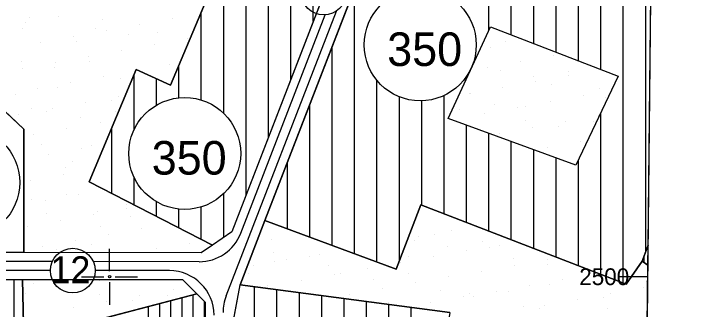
# Model space of a CAD drawing. Extents: x 419109 to 421295, y 4452223 to 4457798.
# Drawn here: x 420957.3 to 421266.4, y 4452485.5 to 4452617.5 of the extents above; entities that cross this region are included whole.
import ezdxf

# ---------------------------------------------------------------- set-up
doc = ezdxf.new("R2010")
doc.units = 0
for name, color, linetype in [('ADA', 7, 'Continuous'), ('ADAKENARI', 7, 'Continuous'), ('Default', 7, 'Continuous'), ('KALDIRIM', 7, 'Continuous'), ('KD_DAIRE', 7, 'Continuous'), ('KD_YGEN', 7, 'Continuous'), ('PAFTALAMA', 7, 'Continuous'), ('PL_AYA_PARK_DINLENME', 7, 'Continuous'), ('PL_KON_MEV_350', 7, 'Continuous'), ('PL_KON_MEV_450', 7, 'Continuous'), ('SM_DAIRE', 7, 'Continuous'), ('SM_TAKS', 7, 'Continuous'), ('TR_ORTAYOGUNKONUT', 7, 'Continuous'), ('TR_PARKALANI', 7, 'Continuous'), ('TR_YUKSEKYOGUNKONUT', 7, 'Continuous')]:
    doc.layers.add(name, color=color, linetype=linetype)

# ---------------------------------------------------------------- blocks, each defined once
blk = doc.blocks.new('POINT_DISPLAY')
at = {"layer": 'Default'}
blk.add_line((0, 0), (0, 0), dxfattribs=at)

msp = doc.modelspace()

# ---------------------------------------------------------------- linework, layer by layer
at = {"layer": 'ADA'}
for p, q in [((421027.16, 4452585.56), (421111.62, 4452786.24)), ((420907.13, 4452617.31), (420961.75, 4452565.87)), ((421151.16, 4452570.72), (421170.06, 4452611.68)), ((421170.06, 4452611.68), (421227.17, 4452589.62)), ((420990.96, 4452542.37), (421011.92, 4452592.54)), ((421011.92, 4452592.54), (421027.16, 4452585.56)), ((421227.17, 4452589.62), (421208.27, 4452549.84)), ((421208.27, 4452549.84), (421151.16, 4452570.72)), ((420961.75, 4452565.87), (420961.75, 4452510.75)), ((421045.97, 4452514.14), (420990.96, 4452542.37)), ((421127.92, 4452503.37), (421138.95, 4452532.12)), ((421138.95, 4452532.12), (421230.72, 4452496.67)), ((421069.4, 4452525.16), (421127.92, 4452503.37)), ((421237.81, 4452506.91), (421240.5, 4452514.11)), ((421230.72, 4452496.67), (421237.81, 4452506.91)), ((421237.81, 4452506.91), (421240.41, 4452505.19)), ((420961.13, 4452498.75), (420961.65, 4452472.06)), ((421151.95, 4452484.07), (421058.29, 4452496.43)), ((420961.65, 4452472.06), (421038.96, 4452492.38))]:
    msp.add_line(p, q, dxfattribs=at)
at = {"layer": 'ADAKENARI'}
for p, q in [((421113.68, 4452672.92), (421054.54, 4452520.01)), ((421069.4, 4452525.16), (421125.97, 4452671.42)), ((421058.29, 4452496.43), (421069.4, 4452525.16)), ((421054.54, 4452520.01), (421045.97, 4452514.14)), ((421045.97, 4452514.14), (421040.93, 4452510.69)), ((420961.75, 4452510.75), (420907.18, 4452510.79)), ((421040.93, 4452510.69), (420961.75, 4452510.75)), ((420915.8, 4452498.79), (420961.13, 4452498.75)), ((420961.13, 4452498.75), (421032.6, 4452498.7)), ((421032.6, 4452498.7), (421038.96, 4452492.38)), ((421054.75, 4452477.11), (421058.29, 4452496.43)), ((421038.96, 4452492.38), (421042.67, 4452488.69)), ((421042.67, 4452488.69), (421043.46, 4452373.99))]:
    msp.add_line(p, q, dxfattribs=at)
at = {"layer": 'KALDIRIM'}
for p, q in [((421052.05, 4452491.39), (421101.28, 4452618.69)), ((421058.62, 4452519.48), (421096.33, 4452616.98)), ((420974.4, 4452506.74), (420878.15, 4452506.82)), ((421039.95, 4452506.69), (420992.72, 4452506.73)), ((420973.56, 4452502.74), (420878.31, 4452502.82)), ((421026.72, 4452502.7), (420993.56, 4452502.73))]:
    msp.add_line(p, q, dxfattribs=at)
for centre, start, end in [((421039.97, 4452526.69), 269.9569, 338.8546), ((421026.71, 4452482.7), 0.3974, 89.9569), ((421070.7, 4452484.17), 158.8546, 180.3974)]:
    msp.add_arc(centre, 20, start, end, dxfattribs=at)
at = {"layer": 'KD_DAIRE'}
for centre in [(421095.66, 4452626.96), (420983.56, 4452502.72)]:
    msp.add_circle(centre, 10, dxfattribs=at)
at = {"layer": 'PAFTALAMA'}
for p, q in [((421000, 4452502.5), (421000, 4452512.5)), ((420987.5, 4452500), (420997.5, 4452500)), ((421002.5, 4452500), (421012.5, 4452500)), ((421240.35, 4452500), (421227.85, 4452500)), ((421240.35, 4452500), (421240.35, 4452500)), ((421000, 4452497.5), (421000, 4452487.5))]:
    msp.add_line(p, q, dxfattribs=at)
msp.add_lwpolyline([(419138.44, 4455021.89), (419108.72, 4452245.78), (421237.47, 4452223.29), (421266.41, 4454999.4)], dxfattribs=at)
msp.add_circle((421000, 4452500), 0.5, dxfattribs=at)
at = {"layer": 'PL_AYA_PARK_DINLENME'}
msp.add_line((421239.55, 4452422.72), (421240.41, 4452505.19), dxfattribs=at)
for points in [[(421111.62, 4452786.24), (421027.16, 4452585.56), (421011.92, 4452592.54), (420990.96, 4452542.37), (421045.97, 4452514.14), (421040.93, 4452510.69), (420961.75, 4452510.75), (420961.75, 4452565.87), (420907.13, 4452617.31), (420862.44, 4452616.65), (420862.05, 4452637.03)], [(421240.41, 4452505.19), (421237.81, 4452506.91), (421230.72, 4452496.67), (421138.95, 4452532.12), (421127.92, 4452503.37), (421069.4, 4452525.16), (421058.29, 4452496.43), (421151.95, 4452484.07), (421150.76, 4452476.19), (421221.66, 4452469.5), (421219.69, 4452425.78), (421239.55, 4452422.72)]]:
    msp.add_lwpolyline(points, dxfattribs=at)
for points in [[(421208.27, 4452549.84), (421151.16, 4452570.72), (421170.06, 4452611.68), (421227.17, 4452589.62)], [(421038.96, 4452492.38), (420961.65, 4452472.06), (420961.13, 4452498.75), (421032.6, 4452498.7)]]:
    msp.add_lwpolyline(points, close=True, dxfattribs=at)
at = {"layer": 'PL_KON_MEV_350'}
for points in [[(421168.9, 4452817.73), (421120.85, 4452691.59), (421113.68, 4452672.92), (421054.54, 4452520.01), (421045.97, 4452514.14), (420990.96, 4452542.37), (421011.92, 4452592.54), (421027.16, 4452585.56), (421111.62, 4452786.24), (421094.47, 4452793.22), (421114.79, 4452841.49)], [(420961.75, 4452510.75), (420907.18, 4452510.79), (420907.13, 4452617.31), (420961.75, 4452565.87)], [(421221.66, 4452469.5), (421219.69, 4452425.78), (421204.43, 4452417.65), (421149.96, 4452423.83), (421144.17, 4452390.8), (421167.72, 4452387.62), (421148.77, 4452268.26), (421066.1, 4452275.66), (421056.07, 4452286.55), (421054.75, 4452477.11), (421058.29, 4452496.43), (421151.95, 4452484.07), (421150.76, 4452476.19)]]:
    msp.add_lwpolyline(points, close=True, dxfattribs=at)
for points in [[(421241.81, 4452639.69), (421138.97, 4452677.31), (421125.97, 4452671.42), (421069.4, 4452525.16), (421127.92, 4452503.37), (421138.95, 4452532.12), (421230.72, 4452496.67), (421237.81, 4452506.91), (421240.5, 4452514.11)], [(421240.5, 4452514.11), (421241.25, 4452585.52), (421241.81, 4452639.69)], [(421208.27, 4452549.84), (421151.16, 4452570.72), (421170.06, 4452611.68), (421227.17, 4452589.62), (421208.27, 4452549.84)]]:
    msp.add_lwpolyline(points, dxfattribs=at)
at = {"layer": 'PL_KON_MEV_450'}
msp.add_line((421240.41, 4452505.19), (421240.5, 4452514.11), dxfattribs=at)
msp.add_lwpolyline([(421240.5, 4452514.11), (421237.81, 4452506.91), (421240.41, 4452505.19)], dxfattribs=at)
msp.add_lwpolyline([(420943.96, 4452333.26), (420890.44, 4452339.16), (420894.07, 4452409.01), (420955.76, 4452406.29), (420930.36, 4452451.2), (420906.49, 4452429.99), (420877.39, 4452460.37), (420915.8, 4452498.79), (420961.13, 4452498.75), (420961.65, 4452472.06), (421038.96, 4452492.38), (421042.67, 4452488.69), (421043.46, 4452373.99), (421023.35, 4452363.2), (421036.05, 4452320.56), (420975.68, 4452283.75), (420939.98, 4452286.94)], close=True, dxfattribs=at)
at = {"layer": 'SM_DAIRE'}
for centre in [(421138.72, 4452603.61), (421033.56, 4452555.08), (420934.87, 4452542.14)]:
    msp.add_circle(centre, 25, dxfattribs=at)
at = {"layer": 'TR_ORTAYOGUNKONUT'}
for p, q in [((421090.96, 4452614.17), (421090.96, 4452737.15)), ((421080.96, 4452588.32), (421080.96, 4452713.39)), ((421070.96, 4452562.46), (421070.96, 4452689.63)), ((421060.96, 4452536.61), (421060.96, 4452665.87)), ((421169.4, 4452610.24), (421169.4, 4452666.18)), ((421179.4, 4452608.07), (421179.4, 4452662.52)), ((421189.4, 4452604.21), (421189.4, 4452658.86)), ((421199.4, 4452600.35), (421199.4, 4452655.21)), ((421209.4, 4452596.49), (421209.4, 4452651.55)), ((421219.4, 4452592.63), (421219.4, 4452647.89)), ((421229.4, 4452497.18), (421229.4, 4452644.23)), ((421050.96, 4452573.03), (421050.96, 4452642.11)), ((421239.4, 4452511.16), (421239.4, 4452640.57)), ((421109.4, 4452510.27), (421109.4, 4452628.58)), ((421040.96, 4452578.96), (421040.96, 4452618.35)), ((421099.4, 4452513.99), (421099.4, 4452602.73)), ((421030.96, 4452579.94), (421030.96, 4452594.59)), ((421010.96, 4452565.77), (421010.96, 4452590.25)), ((421020.96, 4452576.67), (421020.96, 4452588.4)), ((421159.4, 4452588.57), (421159.4, 4452589.57)), ((421119.4, 4452506.54), (421119.4, 4452587.75)), ((421129.4, 4452507.22), (421129.4, 4452580.42)), ((421149.4, 4452528.08), (421149.4, 4452581.01)), ((421089.4, 4452517.71), (421089.4, 4452576.87)), ((421139.4, 4452531.95), (421139.4, 4452578.62)), ((421219.4, 4452501.04), (421219.4, 4452573.26)), ((421159.4, 4452524.22), (421159.4, 4452567.71)), ((421000.96, 4452537.24), (421000.96, 4452566.31)), ((421169.4, 4452520.36), (421169.4, 4452564.05)), ((421179.4, 4452516.5), (421179.4, 4452560.4)), ((421189.4, 4452512.63), (421189.4, 4452556.74)), ((421079.4, 4452521.44), (421079.4, 4452551.02)), ((421199.4, 4452508.77), (421199.4, 4452553.09)), ((421209.4, 4452504.91), (421209.4, 4452552.22)), ((421010.96, 4452532.11), (421010.96, 4452544.39)), ((421050.96, 4452517.56), (421050.96, 4452537.13)), ((421020.96, 4452526.98), (421020.96, 4452533.48)), ((421030.96, 4452521.85), (421030.96, 4452530.21)), ((421040.96, 4452516.72), (421040.96, 4452531.2)), ((421064.75, 4452277.13), (421064.75, 4452495.58)), ((421074.75, 4452406.61), (421074.75, 4452494.26)), ((421084.75, 4452419.17), (421084.75, 4452492.94)), ((421094.75, 4452422.9), (421094.75, 4452491.62)), ((421104.75, 4452422.29), (421104.75, 4452490.3)), ((421114.75, 4452416.95), (421114.75, 4452488.98)), ((421124.75, 4452270.41), (421124.75, 4452487.66)), ((421134.75, 4452269.52), (421134.75, 4452486.34))]:
    msp.add_line(p, q, dxfattribs=at)
at = {"layer": 'TR_YUKSEKYOGUNKONUT'}
for p, q in [((421238.77, 4452506.27), (421238.77, 4452509.48)), ((420957.39, 4452285.38), (420957.39, 4452498.76)), ((421027.39, 4452365.37), (421027.39, 4452489.34)), ((421032.39, 4452368.05), (421032.39, 4452490.65)), ((421037.39, 4452370.73), (421037.39, 4452491.97)), ((421017.39, 4452309.18), (421017.39, 4452486.71)), ((421022.39, 4452312.23), (421022.39, 4452488.03)), ((421042.39, 4452373.41), (421042.39, 4452488.97))]:
    msp.add_line(p, q, dxfattribs=at)

# ---------------------------------------------------------------- block references
at = {"layer": 'TR_PARKALANI', "xscale": 0.1, "yscale": 0.10000000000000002}
for p in [(420964.23, 4452615.94), (420977.21, 4452616.39), (420962.44, 4452613.79), (420996.93, 4452614.77), (421028.19, 4452615.23), (420961.1, 4452610.81), (420993.77, 4452610.73), (420998.64, 4452610.02), (421013.41, 4452612.62), (420983.87, 4452607.41), (421008.54, 4452608.13), (421021.28, 4452609.09), (420969.1, 4452604.81), (420985.44, 4452605.13), (421020.07, 4452603.64), (421034.85, 4452606.25), (421176.94, 4452605.16), (421005.3, 4452601.04), (421170.25, 4452602.23), (420990.53, 4452598.43), (421198.38, 4452598.79), (420960.75, 4452596.24), (420975.76, 4452595.83), (420991.17, 4452595.96), (421026.74, 4452594.66), (421183.6, 4452596.18), (420960.99, 4452593.22), (420975.52, 4452593.64), (421168.83, 4452593.58), (421174.4, 4452591.93), (421204.82, 4452591.65), (421219.81, 4452592.41), (420997.19, 4452589.45), (421005.07, 4452588.43), (421189.18, 4452589.33), (421205.04, 4452589.81), (420982.42, 4452586.85), (421190.26, 4452587.2), (421197.2, 4452585.68), (420967.65, 4452584.24), (420976.55, 4452584.61), (421160.72, 4452581.99), (421175.49, 4452584.6), (421218.72, 4452584.12), (420958.15, 4452581.47), (421000.9, 4452578.93), (421003.85, 4452580.47), (421161.36, 4452581.72), (421211.7, 4452580.83), (421221.54, 4452580), (420989.08, 4452577.87), (421171.8, 4452577.16), (421182.15, 4452575.62), (421185.7, 4452576.04), (421196.93, 4452578.22), (420959.54, 4452572.66), (420965.06, 4452574.97), (420972.05, 4452573.94), (420974.31, 4452575.26), (421002.46, 4452573.66), (421156.16, 4452574.84), (421167.38, 4452573.01), (420986.82, 4452571.34), (421152.61, 4452570.41), (421185.7, 4452569.63), (421218.36, 4452571.85), (420995.74, 4452568.89), (421188.81, 4452566.64), (421200.47, 4452567.03), (421203.59, 4452569.24), (421216.11, 4452569.35), (420966.2, 4452563.68), (420980.97, 4452566.28), (421174.04, 4452564.03), (421210.25, 4452560.26), (420969.45, 4452559.17), (420987.63, 4452557.3), (420992, 4452558.42), (421195.47, 4452557.66), (421212.65, 4452559.48), (420972.86, 4452554.7), (420983.35, 4452551.64), (420980.51, 4452548.78), (420979.52, 4452545.72), (420964.74, 4452543.12), (420980.75, 4452536.87), (420986.18, 4452536.74), (420965.11, 4452534.55), (420971.41, 4452534.14), (420994.65, 4452529.34), (421007.46, 4452532.22), (421007.61, 4452530.37), (420971.62, 4452528.26), (420992.84, 4452527.76), (421009.42, 4452526.74), (420978.07, 4452525.16), (420963.29, 4452522.55), (420995.97, 4452522.58), (421014.27, 4452521.39), (421152.72, 4452520.51), (420999.5, 4452518.78), (421137.95, 4452517.91), (421145.09, 4452518.78), (420984.73, 4452516.18), (420992.05, 4452514.57), (421035.7, 4452515.01), (421072.2, 4452516.47), (421136.27, 4452515.99), (421166.68, 4452515.71), (421174.16, 4452514.14), (420969.95, 4452513.57), (420976.41, 4452512.25), (421020.93, 4452512.41), (421073.42, 4452510.85), (421151.04, 4452513.39), (421159.38, 4452511.53), (421169.44, 4452513.1), (421089.34, 4452509.03), (421093.63, 4452510.09), (421133.6, 4452509.14), (421144.61, 4452508.93), (421180.58, 4452508.18), (421195.59, 4452507.76), (421064.09, 4452504.88), (421073.7, 4452506.71), (421078.86, 4452507.49), (421097.76, 4452505.17), (421129.84, 4452506.32), (421180.82, 4452505.16), (421195.35, 4452505.57), (421103.25, 4452501.5), (421115.07, 4452503.72), (421166.04, 4452502.55), (421061.93, 4452501.21), (421085.52, 4452498.51), (421100.29, 4452501.11), (421118.02, 4452498.9), (421133.66, 4452501.22), (421151.27, 4452499.95), (421202.25, 4452498.78), (421217.02, 4452501.39), (420966.13, 4452497.06), (420977.35, 4452495.23), (420992.13, 4452497.84), (420995.68, 4452498.26), (421070.75, 4452495.9), (421136.5, 4452497.34), (421187.48, 4452496.18), (421196.38, 4452496.55), (421239.67, 4452497.76), (420962.58, 4452492.63), (421028.33, 4452494.07), (421106.96, 4452492.13), (421121.73, 4452494.74), (421147.56, 4452493.69), (421160.54, 4452492.58), (421172.7, 4452493.57), (421177.98, 4452493.41), (421223.68, 4452492.41), (421238.45, 4452495.01), (420995.68, 4452491.85), (421010.45, 4452489.25), (421013.56, 4452491.46), (421026.09, 4452491.57), (421157.93, 4452490.97), (421162.34, 4452491.09), (421208.91, 4452489.8), (421220.73, 4452490.87), (420984.02, 4452486.25), (420998.79, 4452488.86), (421124.71, 4452488.62), (421143.16, 4452488.36), (421184.89, 4452486.9), (421194.14, 4452487.2), (421191.88, 4452485.88), (421222.29, 4452485.59)]:
    msp.add_blockref('POINT_DISPLAY', p, dxfattribs=at)

# ---------------------------------------------------------------- texts
at = {"layer": 'KD_YGEN'}
msp.add_text('12', height=12, dxfattribs=at).set_placement((420973.58, 4452497.11))
at = {"layer": 'PAFTALAMA'}
msp.add_text('2500', height=7.5, dxfattribs=at).set_placement((421209.73, 4452496.25))
at = {"layer": 'SM_TAKS'}
for p in [(421123.98, 4452594.17), (421018.82, 4452545.63)]:
    msp.add_text('350', height=15, dxfattribs=at).set_placement(p)

doc.saveas('drawing.dxf')
